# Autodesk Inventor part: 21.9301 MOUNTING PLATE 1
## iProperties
Created: 2011-01
Part Number: 21.9301 MOUNTING PLATE 1
Document SubType Name: Modeling
Designer: Administrator
Density: 7.85 g/cm^3
Material: Steel
Mass: 214.225 g
Surface Area: 192.305 cm^2
Volume: 27.2898 cm^3
Author: Administrator
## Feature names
1. Revolution1
2. Shell1
3. Extrusion1
4. Extrusion2
5. Extrusion3
6. Extrusion4
7. Mirror1
